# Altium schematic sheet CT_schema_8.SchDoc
size 278 x 170 mm
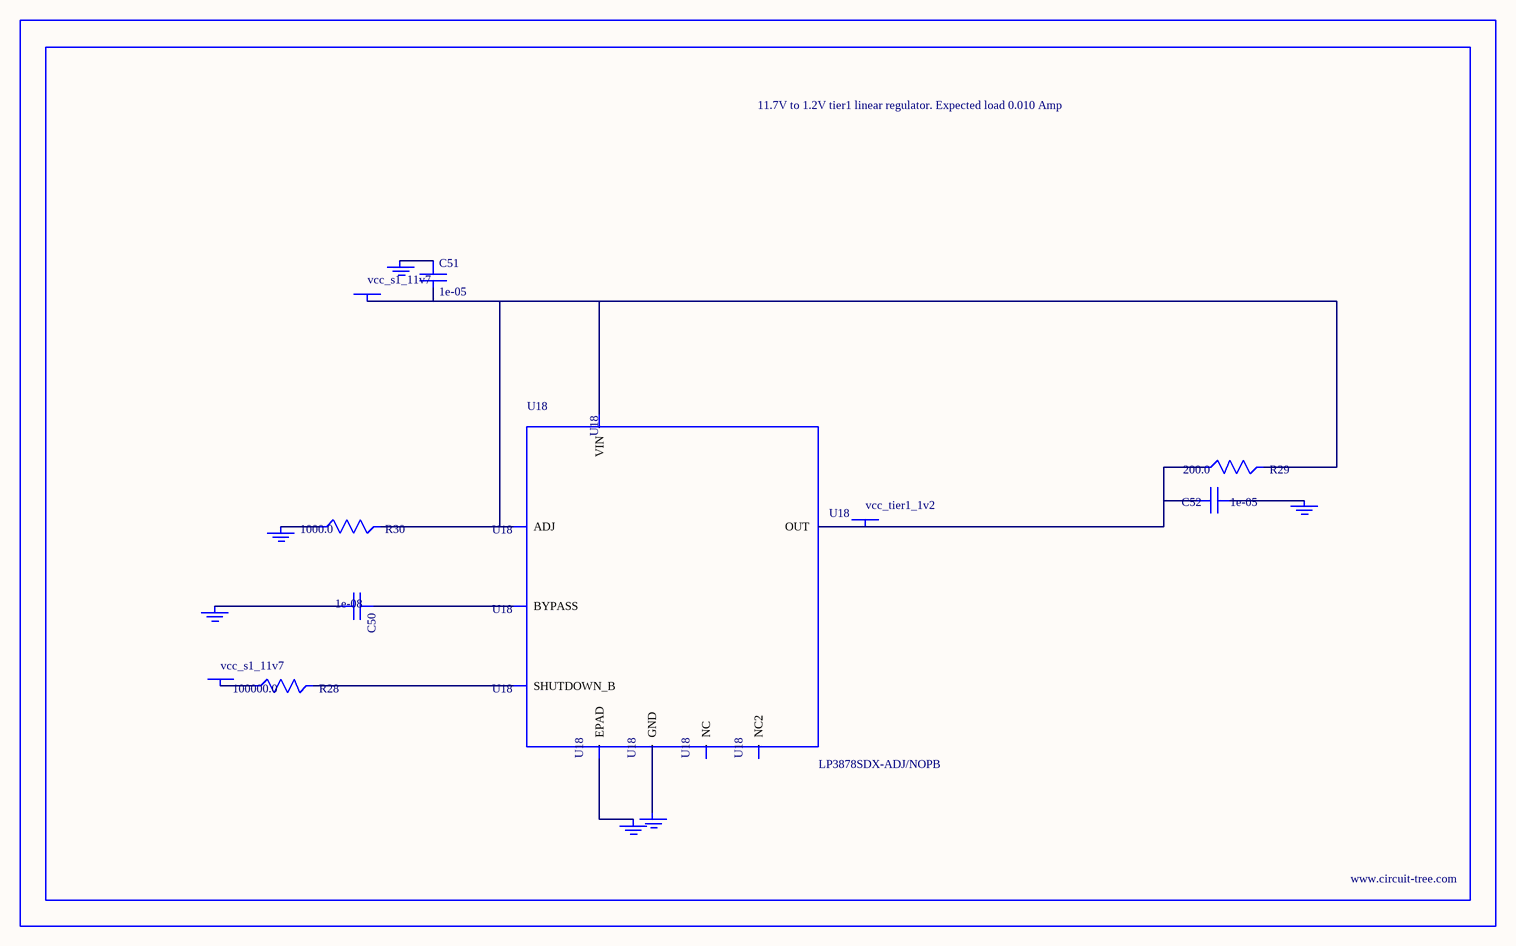
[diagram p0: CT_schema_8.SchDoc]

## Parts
BORDER7  (no value)
C50  1e-08  [C0402]
C51  1e-05  [C1210]
C52  1e-05  [C0805]
GND_INSTANCE_7_0  (no value)
GND_INSTANCE_7_1  (no value)
GND_INSTANCE_7_2  (no value)
GND_INSTANCE_7_3  (no value)
GND_INSTANCE_7_4  (no value)
GND_INSTANCE_7_5  (no value)
POWER_INSTANCE_7_0  vcc_s1_11v7
POWER_INSTANCE_7_1  vcc_s1_11v7
POWER_INSTANCE_7_2  vcc_tier1_1v2
R28  100000.0  [R0603]
R29  200.0  [R0603]
R30  1000.0  [R0603]
U18  LP3878SDX-ADJ/NOPB  [WSON-8]

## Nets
NetC50_1: C50.1 U18.1(BYPASS)
NetC50_2: C50.2 GND_INSTANCE_7_0.0(GND)
NetC51_1: C51.1 GND_INSTANCE_7_1.0(GND)
NetC51_2: C51.2 POWER_INSTANCE_7_0.0(PWR) R29.2 R30.2 U18.4(VIN) U18.6(ADJ)
NetC52_1: C52.1 GND_INSTANCE_7_2.0(GND)
NetC52_2: C52.2 POWER_INSTANCE_7_2.0(PWR) R29.1 U18.5(OUT)
NetGND_INSTANCE_7_3_0: GND_INSTANCE_7_3.0(GND) R30.1
NetGND_INSTANCE_7_4_0: GND_INSTANCE_7_4.0(GND) U18.PAD(EPAD)
NetGND_INSTANCE_7_5_0: GND_INSTANCE_7_5.0(GND) U18.3(GND)
NetPOWER_INSTANCE_7_1_0: POWER_INSTANCE_7_1.0(PWR) R28.1
NetR28_2: R28.2 U18.8(SHUTDOWN_B)

Not connected (* = marked no-connect by the designer): U18 2(NC) 7(NC2)

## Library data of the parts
BORDER7 = BORDER_PAGE7
C50 = C0402C103K3RAC
C51 = C1210C106K5PACTU
C52 = GRM219R60J106ME19D
GND_INSTANCE_7_0-GND_INSTANCE_7_5 = GND
POWER_INSTANCE_7_0-POWER_INSTANCE_7_2 = PWR
R28 = RC0603JR-07100KL
R29 = RC0603JR-07200RL
R30 = RC0603JR-071KL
